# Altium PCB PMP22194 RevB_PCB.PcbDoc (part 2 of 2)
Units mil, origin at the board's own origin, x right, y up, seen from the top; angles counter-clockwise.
Board outline 2100 x 2100 mil, 4 copper layers (Top Layer, Signal Layer 1, Signal Layer 2, Bottom Layer), stack 62.2 mil thick; 70 components, 29 nets, 172 pads, 172 vias.
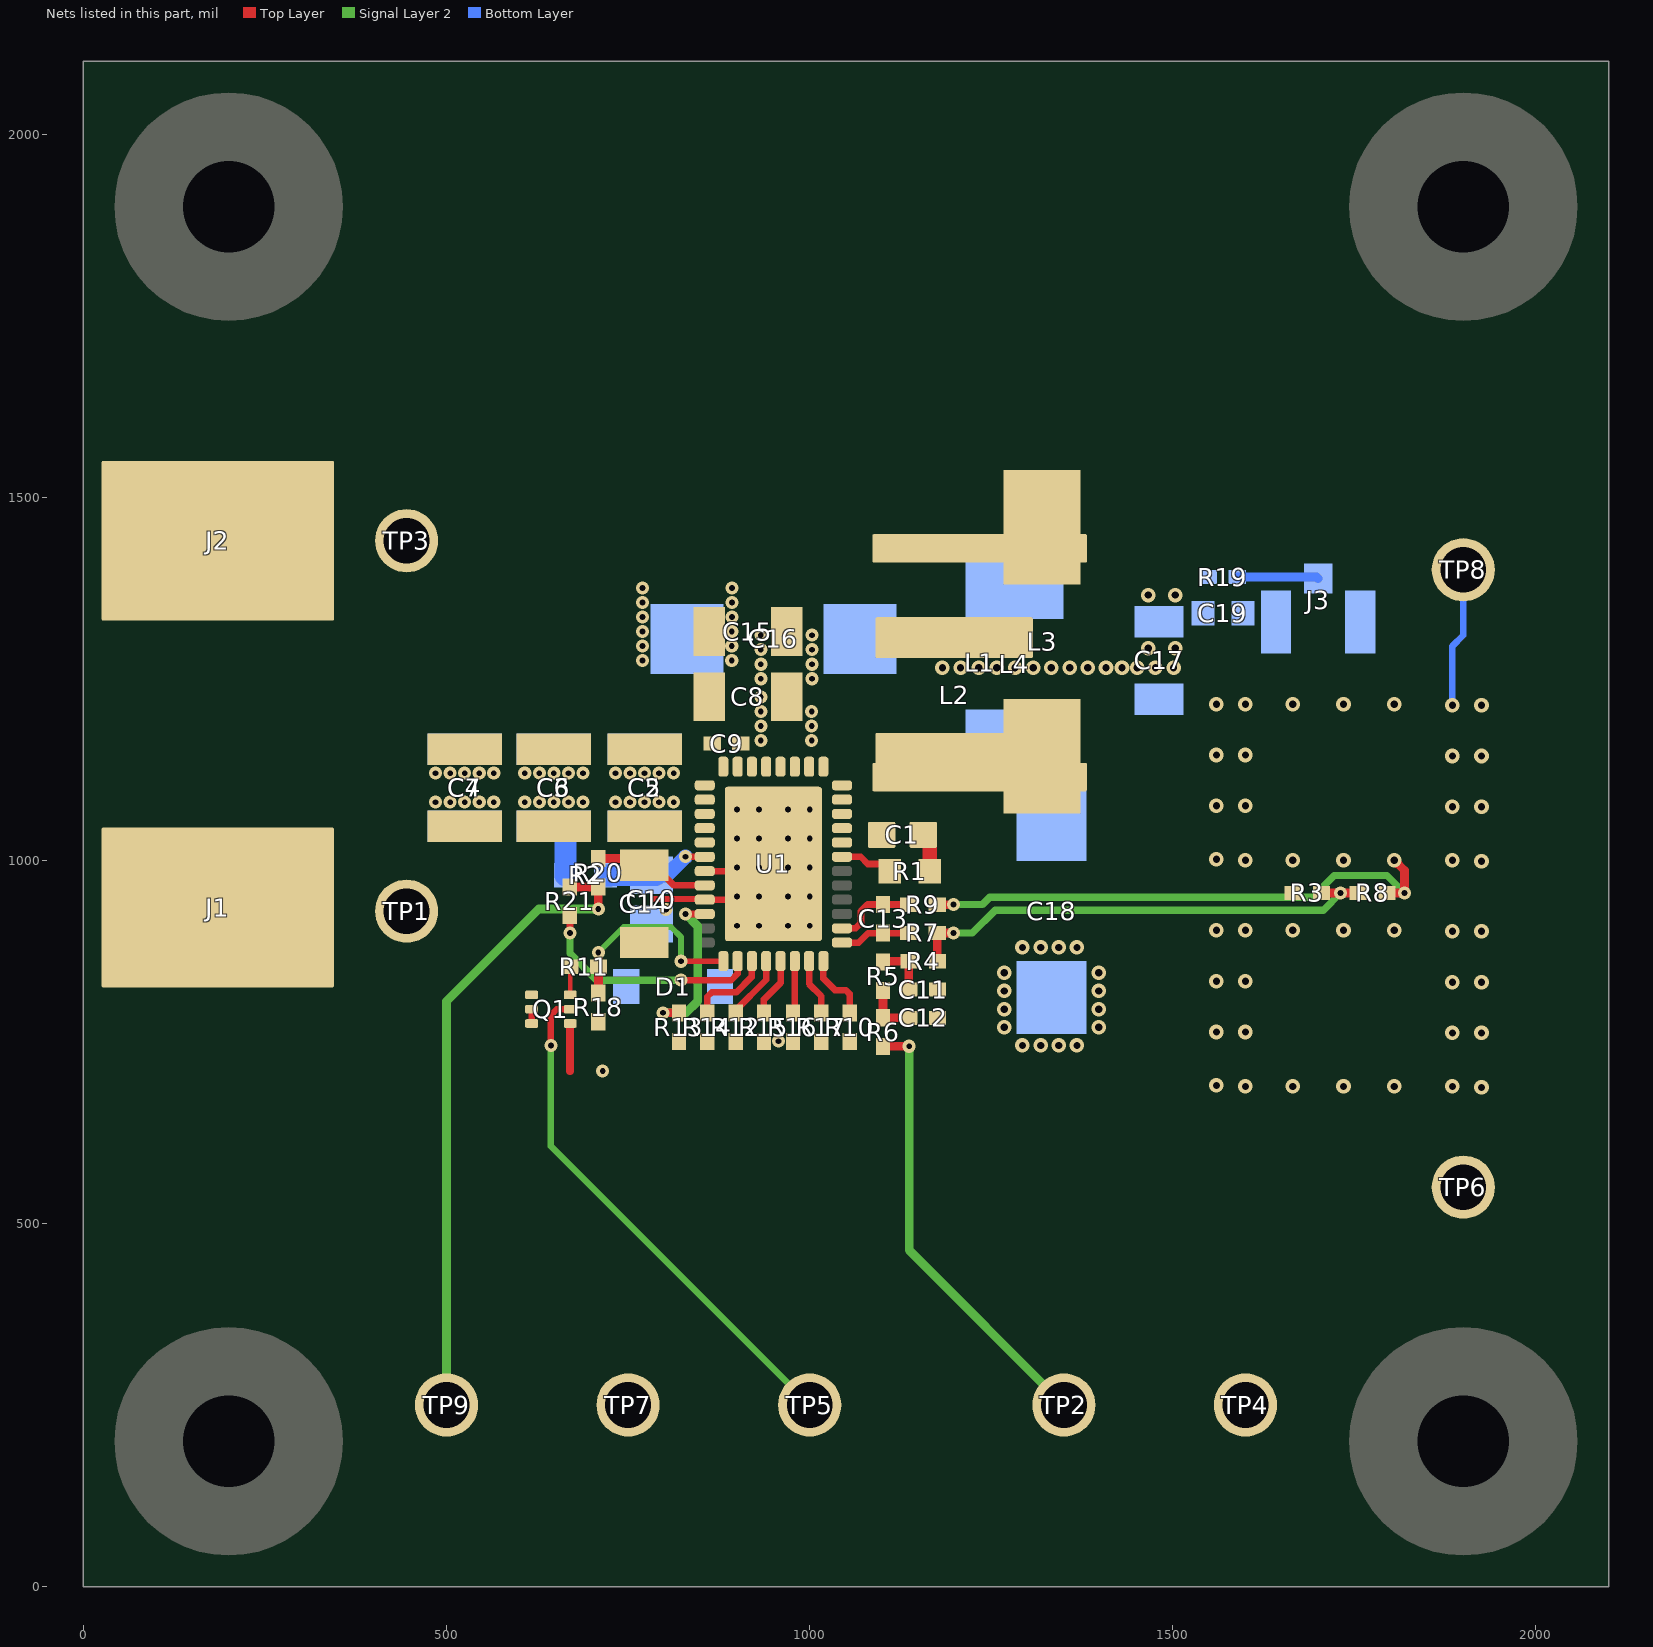
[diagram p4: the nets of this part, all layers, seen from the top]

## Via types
v1: diameter 20, hole 10, Top Layer to Bottom Layer, tented both sides, 78 vias
v2: diameter 18, hole 8, Top Layer to Bottom Layer, tented both sides, 72 vias
v3: diameter 18, hole 8, Top Layer to Bottom Layer, 20 vias
v4: diameter 18, hole 8, Top Layer to Bottom Layer, tented top, 2 vias

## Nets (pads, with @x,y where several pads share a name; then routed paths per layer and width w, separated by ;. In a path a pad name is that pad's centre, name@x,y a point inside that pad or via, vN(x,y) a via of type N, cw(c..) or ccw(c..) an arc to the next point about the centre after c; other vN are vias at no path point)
+Vin: C2.1 C3.1 C4.1 C5.1 C6.1 C7.1 C8.1 C9.1 J1.1 Q1.1 R2.2 TP1.1 U1.21 U1.22 U1.23 U1.24 U1.25 | length 74.3
  Bottom Layer w30: C6.1@647.72,1046.85 663.94,1030.63 R2.2@663.94,979.28
  other v2: 485,1080 505,1080 525,1080 545,1080 565,1080 607.72,1080 627.72,1080 647.72,1080 667.72,1080 687.72,1080 732.72,1080 752.72,1080 772.72,1080 792.72,1080 812.72,1080
-V: C8.2 C9.2 C10.2 C14.2 C15.2 C16.2 D1.2 L4.1 R10.1 R12.1 R13.1 R14.1 R15.2 R16.1 R17.1 R18.1 U1.13 U1.14 U1.15 U1.16 U1.17 U1.18 U1.19 U1.20 U1.27 U1.29 U1.41@950,995 | length 270.5
  Top Layer w8: 785.12,946.88 838.94,946.88 838.94,946.71 854.59,946.71 U1.29@855.51,945.79
  Top Layer w9: U1.29@855.51,945.79 900.79,945.79 U1.41@940.16,985.16 ; U1.27@855.51,985.16 U1.41@940.16,985.16 ; U1.41@950,995 U1.41@940.16,985.16
  other v2: 932.72,1165 1002.72,1165 932.72,1185 1002.72,1185 932.72,1205 1002.72,1205 932.72,1225 932.72,1250 1003,1250 932.72,1270 1003,1270 932.72,1290 1003,1290 932.72,1310 1003,1310
  other v3: 900,910 930,910 970,910 1000,910 900,950 930,950 970,950 1000,950 900,990 930,990 970,990 1000,990 900,1030 930,1030 970,1030 1000,1030 900,1070 930,1070 970,1070 1000,1070
  other v4: 957,751 802,932
-Vo_adj: R6.2 TP2.1 | length 618.3
  Top Layer w12: R6.2@1101,743.81 1101.19,744 v2(1137,744)
  Signal Layer 2 w12: v2(1137,744) 1137,463 TP2.1@1350,250
-Vout: C17.2 C18.2 C19.2 J3.2@1641.93,1328 J3.3@1758.07,1328 L4.2 R8.1 R9.1 TP8.1 | length 937.5
  Top Layer w12: R9.1@1175.68,939 v2(1198,939) ; R8.1@1794.68,955 v2(1819,955) 1819,986 v1(1805,1000)
  Signal Layer 2 w10: v2(1198,939) 1237.73,939 1247.91,949.18 1692.4,949.18 1722.22,979 1795,979 v2(1819,955)
  Bottom Layer w9: v1(1885,1213.63) 1885,1295 1900,1310 TP8.1@1900,1400
  other v1: 1925,998.63 1600,1000 1665,1000 1735,1000 1885,1000 1560,1001.37 1885,1073.63 1925,1073.63 1560,1075 1600,1075 1885,1143.63 1925,1143.63 1560,1145 1600,1145 1925,1213.63 1560,1215 1600,1215 1665,1215 1735,1215 1805,1215
BP: C14.1 R20.2 U1.28 | length 161.8
  Top Layer w9: C14.1@772,993.15 785.51,993.15 813.19,965.47 U1.28@855.51,965.47
  Top Layer w12: R20.2@709,1002.4 762.75,1002.4 C14.1@772,993.15
EN: R11.1 R18.2 U1.33 | length 281.6
  Top Layer w8: v2(823,861) 823.14,861.14 U1.33@881.1,861.14
  Top Layer w12: R18.2@708.72,817.19 709.18,817.65 R11.1@709.18,853.28 709,853.47 v2(709,873)
  Signal Layer 2 w8: v2(709,873) 744.11,908.11 808.89,908.11 823,894 v2(823,861)
GND: C2.2 C3.2 C4.2 C5.2 C6.2 C7.2 C11.2 C12.2 C15.1 C16.1 C17.1 C18.1 C19.1 D1.1 J2.1 L1.2 L2.2 L3.2 Q1.4 R3.2 R19.1 TP3.1 TP4.1 TP6.1 TP7.1 | length 65.7
  Top Layer w11: 670.29,709.57 Q1.4@670.29,775.32
  other v1: 1925,687.25 1600,688.63 1665,688.63 1735,688.63 1805,688.63 1885,688.63 1560,690 1293,745.09 1318,745.09 1343,745.09 1368,745.09 1885,762.25 1925,762.25 1560,763.63 1600,763.63 1268,770.09 1398,770.09 1268,795.09 1398,795.09 1268,820.09 1398,820.09 1885,832.25 1925,832.25 1560,833.63 1600,833.63 1268,845.09 1398,845.09 1293,880.09 1318,880.09 1343,880.09 1368,880.09 1885,902.25 1925,902.25 1560,903.63 1600,903.63 1665,903.63 1735,903.63 1805,903.63 1182.72,1265 1207.72,1265 1232.72,1265 1257.72,1265 1282.72,1265 1307.72,1265 1332.72,1265 1358,1265 1383,1265 1408,1265 1430,1265 1451,1265.15 1476,1265.15 1501,1265.15 1466.28,1292.15 1503.28,1292.15 1466,1365.15 1503.28,1365.15
  other v2: 715,710 485,1120 505,1120 525,1120 545,1120 565,1120 607.72,1120 627.72,1120 647.72,1120 667.72,1120 687.72,1120 732.72,1120 752.72,1120 772.72,1120 792.72,1120 812.72,1120 770,1275 892.72,1275 770,1295 892.72,1295 770,1315 892.72,1315 770,1335 893,1335 770,1355 893,1355 770,1375 893,1375
ILIM: R13.2 U1.30 | length 230.1
  Top Layer w9: v2(828.99,926.01) 829.08,926.1 U1.30@855.51,926.1
  Top Layer w12: v2(798,790) 819.69,790 R13.2@820,789.69
  Signal Layer 2 w12: v2(798,790) 829.79,790 845.87,806.08 845.87,909.13 v2(828.99,926.01)
MODE: R17.2 U1.39 | length 78.4
  Top Layer w9: U1.39@999.21,861.14 999.21,829.79 1016,813 R17.2@1016,789.69
NetC1_2: C1.2 R1.2 | length 53.7
  Top Layer w20: C1.2@1156.34,1035 1165.28,1026.06 R1.2@1165.28,985
NetC11_1: C11.1 R4.2 R5.1 | length 75
  Top Layer w12: R5.1@1101,860.18 1101.82,861 R4.2@1136.53,861 1136.53,822.28 C11.1@1136.82,822
NetC12_1: C12.1 R5.2 R6.1 | length 73.7
  Top Layer w12: R5.2@1101,820.81 R6.1@1101,783.18 1136.26,783.18 1136.63,782.81 C12.1@1136.82,783
NetJ3_1: J3.1 R19.2 | length 112.1
  Bottom Layer w12: R19.2@1588.69,1390 1698.04,1390 J3.1@1700,1388.04
NetQ1_2: Q1.2 Q1.3 | length 19.7
  Top Layer w9: Q1.3@617.14,775.32 Q1.2@617.14,795
NetQ1_5: Q1.5 TP5.1 | length 714.5
  Top Layer w9: v2(643.72,745) 643.72,787.05 651.67,795 Q1.5@670.29,795
  Signal Layer 2 w9: v2(643.72,745) 643.72,606.28 TP5.1@1000,250
NetQ1_6: Q1.6 R11.2 | length 38.8
  Top Layer w6: R11.2@669.81,853.28 670.29,852.81 Q1.6@670.29,814.68
NetR1_1: R1.1 U1.7 | length 73.9
  Top Layer w9: U1.7@1044.49,1004.84 1070.16,1004.84 1080.08,994.92 1100.24,994.92 R1.1@1110.16,985
Pgd: R21.1 U1.34 | length 320.3
  Top Layer w9: v2(823,835) 891.99,834.99 900.79,843.79 U1.34@900.79,861.14
  Top Layer w10: R21.1@669.72,923.82 670,923.53 v2(670,900) 670.43,900 v2@671,900.57
  Signal Layer 2 w10: v2(670,900) 670,872 707,835 v2(823,835)
Pgood: R20.1 R21.2 TP9.1 | length 887
  Top Layer w12: R21.2@669.72,963.19 708.85,963.19 R20.1@709,963.03 v2(709,933)
  Signal Layer 2 w12: TP9.1@500,250 500,806 627,933 v2(709,933)
RAMP: R10.2 U1.40 | length 95.2
  Top Layer w9: U1.40@1018.9,861.14 1018.9,837.1 1034.7,821.3 1049.7,821.3 1055,816 R10.2@1055,789.69
RSN: C13.2 R9.2 U1.2 | length 115
  Top Layer w9: U1.2@1044.49,906.42 1063.23,906.42 1070.64,913.83 1070.64,930.12 1079.7,939.19 C13.2@1101,939.19 1136.13,939.19 R9.2@1136.31,939
RSP: C13.1 R7.2 U1.1 | length 97.3
  Top Layer w9: U1.1@1044.49,886.73 1067.4,886.73 1080.49,899.82 C13.1@1101,899.82 1136.13,899.82 R7.2@1136.31,900
RT: R16.2 U1.38 | length 72.5
  Top Layer w9: R16.2@977,789.69 979.53,792.21 U1.38@979.53,861.14
SS: R15.1 U1.37 | length 80.9
  Top Layer w9: R15.1@937,789.68 937,808.42 959.84,831.26 U1.37@959.84,861.14
SW: C1.1 L1.1 L2.1 L3.1 U1.8 U1.9 U1.10 U1.11 U1.12
SYNC: R14.2 U1.35 | length 116.8
  Top Layer w9: R14.2@859,789.69 859,812 865.12,818.12 898.98,818.12 920.05,839.19 920.05,860.72 U1.35@920.47,861.14
VDD: C10.1 R2.1 U1.26 | length 147.4
  Top Layer w9: v2(829,1005) 829.16,1004.84 U1.26@855.51,1004.84
  Bottom Layer w20: C10.1@788,979.46 803.46,979.46 v2(829,1005)
  Bottom Layer w30: R2.1@719.06,979.28 C10.1@788,979.46 ; R2.1@725.06,979.28 R2.1@725.24,979.46
VFB: R3.1 R4.1 R7.1 R8.2 | length 667.8
  Top Layer w12: R4.1@1175.9,861 1175.68,861.22 R7.1@1175.68,900 v2(1198,900) ; R3.1@1704.68,955 v2(1731,955) R8.2@1755.31,955
  Signal Layer 2 w10: v2(1198,900) 1224,900 1255.31,931.31 1707.31,931.31 v2(1731,955)
VSEL: R12.2 U1.36 | length 88.9
  Top Layer w9: R12.2@898,789.69 898,793.28 940.16,835.44 U1.36@940.16,861.14
pads on no net: H1.1 H2.1 H3.1 H4.1 H5.0 H6.0 H7.0 H8.0 J3.2@1640.94,1328 J3.3@1759.06,1328 LBL1.0 U1.3 U1.4 U1.5 U1.6 U1.31 U1.32 U1.41@917.91,919.41 U1.41@917.91,969.8 U1.41@917.91,1020.2 U1.41@917.91,1070.59 U1.41@982.09,919.41 U1.41@982.09,969.8 U1.41@982.09,1020.2 U1.41@982.09,1070.59

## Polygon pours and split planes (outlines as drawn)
-V on Top Layer "TOP_LAYER_-V2" (solid, remove dead copper, pour order 6): 737,800 727,790 699,790 699,760 740,760 763,737 1066,737 1066,770 807,770 807,924 822,939 868,939 868,953 737,953
-V on Top Layer "TOP_LAYER_-V1" (solid, remove dead copper, pour order 4): 883,889 883,939 844,939 841,942 841,950 844,953 883,953 883,978 844,978 841,981 841,989 844,992 883,992 883,1115 877,1115 874,1118 874,1140 877,1143 893,1143 893,1173 918,1198 918,1350 1017,1350 1017,1143 1023,1143 1026,1140 1026,1117 1023,1114 1017,1114 1017,891 1015,889
-Vout on Top Layer "TOP_LAYER_-Vout" (solid, remove dead copper, pour order 12): 1525,1245 2080,1245 2080,980 1525,980
GND on Top Layer "TOP_LAYER_GND" (solid, remove dead copper, pour order 14): 1164,750 1164,835 1200,835 1200,1055 1407.72,1055 1407.72,1195 1025,1195 1025,1245 902.72,1245 832.72,1245 827.72,1240 827.72,1120 817.72,1110 0,1110 0,2100 2100,2100 2100,0 1205,0 0,0 0,750
+Vin on Top Layer "TOP_LAYER_+VIN" (solid, remove dead copper, pour order 10): 590,810 625,810 625,965 685,1025 827.72,1025 834.72,1018 870.72,1018 870.72,1148 882.72,1160 882.72,1230 837.72,1230 837.72,1157.6 837.72,1105 827.72,1095 0,1095 0,775 590,775
SW on Top Layer "TOP_LAYER_SW" (solid, remove dead copper, pour order 2): 1031,1103 1031,1131 1080,1180 1260,1180 1260,1225 1385,1225 1385,1165 1385,1090 1132.72,1090 1117.72,1075 1117.72,1018 1031,1018
GND on Bottom Layer "BOTTOM_LAYER_GND" (solid, remove dead copper, pour order 26): 0.63,2102 2100.63,2102 2100.63,2 0.63,2
-Vout on Bottom Layer "BOTTOM_LAYER_-Vout" (solid, remove dead copper, pour order 24): 1580,1245 1580,1370 1780,1370 1780,1245 1950,1245 1950,980 1290,980 1167.72,1102.28 1167.72,1240 1172.72,1245
-V on Bottom Layer "BOTTOM_LAYER_-V" (solid, remove dead copper, pour order 22): 860,800 845,815 845,855 825,875 797,875 746.03,875 746.19,939.85 831,940 850,959 850,978 850,1167.28 917.72,1235 917.72,1317.72 1035,1435 1355,1435 1355,1322.28 1322.72,1290 1162.72,1290 1027.72,1155 1027.72,960 1097.72,890 1097.72,800
+Vin on Bottom Layer "Bottom_LAYER_+VIN" (solid, remove dead copper, pour order 20): 827.72,1025 737.72,1025 470,1025 470,1095 577.72,1095 827.72,1095
-V on Signal Layer 1 "SIGNAL_LAYER_-V" (solid, remove dead copper, pour order 16): 0,0 0,2100 2100,2100 2100,0
GND on Signal Layer 2 "SIGNAL_LAYER_2_GND" (solid, remove dead copper, pour order 18): 0,0 0,2100 2100,2100 2100,0

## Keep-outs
Keep-Out Layer:
  text ".Layer_Name" at 577,-858.49 h60

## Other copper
Top Layer:
  text ".Layer_Name" at 577,-858.49 h60
Bottom Layer:
  text ".Layer_Name" at 577,-858.49 h60

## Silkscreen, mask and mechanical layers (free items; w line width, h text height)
Top Overlay:
  lines w5: 670,943 670,944 ; 689,853 690,853 ; 709,797 709,798 ; 709,982 709,983 ; 860,770 860,771 ; 885,1160 886,1160 ; 938,770 938,771 ; 977,770 977,771 ; 1016,770 1016,771 ; 1101,763 1101,764 ; 1101,840 1101,841 ; 1101,919 1101,920 ; 1125.5,1036 1131,1036 ; 1156,783 1157,783 ; 1156,822 1157,822 ; 1156,861 1157,861 ; 1156,900 1157,900 ; 1156,939 1157,939 ; 1684.5,955 1685.5,955 ; 1775,955 1776,955
  text "'.PRJ_Number'.PCB_Rev" at 797.88,1905 h108.27
  text "-Vout" at 1651,1278 h72.83
  text "GND" at 1673,606 h72.83
  text ".Layer_Name" at 577,-858.49 h60
Bottom Overlay:
  lines w5: 691,980 692,980
  text ".Layer_Name" at 577,-858.49 h60
Top Paste:
  text ".Layer_Name" at 577,-858.49 h60
Bottom Paste:
  text ".Layer_Name" at 577,-858.49 h60
Top Solder:
  rectangle: 1615,705 1870,885
  rectangle: 1615,1020 1870,1200
  text ".Layer_Name" at 577,-858.49 h60
  text ".Layer_Name" at 577,-858.49 h60
Bottom Solder:
  text ".Layer_Name" at 577,-858.49 h60
Drill Guide:
  text ".Layer_Name" at 577,-858.49 h60
M1 Board Outline:
  the board outline again, w10
  text ".Layer_Name" at 577,-858.49 h60
M2 Board Dimensions:
  rectangle: 0,-275 125,-150
  rectangle: 125,-400 500,-275
  lines w7: 0,-275 1000,-275 ; 125,-400 125,-150 ; 250,-400 250,-150 ; 500,-400 500,-150 ; 750,-400 750,-150 ; 0,-400 1000,-400 1000,-150 0,-150 0,-400
  text ".Layer_Name" at 577,-858.49 h60
M3 3D STEP Top:
  text ".Layer_Name" at 577,-858.49 h60
M4 3D STEP Bottom:
  text ".Layer_Name" at 577,-858.49 h60
M5 Assembly Top:
  lines w10: -292,-930.17 6308,-930.17 ; -292,-726.83 6310,-726.83 ; -292,-523.5 -292,-1133.5 3713,-1133.5 6310,-1133.5 6310,-523.5 -291.5,-523.5 -291.5,-1133.5 1284,-1133.5 ; 2173,-1133.5 2173,-523.5 ; 3440,-726.83 3440,-523.5 ; 4280,-726.83 4280,-523.5 ; 4902,-1140 4902,-937.17
  text "COMPONENTS MARKED 'DNP' SHOULD NOT BE POPULATED." at 1153.5,-318.5 h60
  text "ASSEMBLY VARIANT:" at 1153,-434 h60
  text ".VariantName" at 2189,-434 h60
  text "PCB VIEWED FROM TOP SIDE" at -228.5,-655.67 h60
  text "BOARD #:" at 2248,-655.67 h60
  text ".PRJ_Number" at 2793.5,-655.67 h60
  text "REV:" at 3638,-655.67 h60
  text ".PCB_Rev" at 3929.5,-655.67 h60
  text "SVN REV:" at 4476,-655.67 h60
  text ".VersionControl_RevNumber" at 4982,-655.67 h60
  text "TID #:" at 2248,-859 h60
  text ".TID" at 2793.5,-859 h60
  text "PLOT NAME =" at -228.5,-1064.34 h60
  text ".plot_File_Name" at 577,-1064.34 h60
  text "GENERATED    :" at 2250,-1064.34 h60
  text ".Print_Date" at 3119.5,-1064.34 h60
  text ".Print_Time" at 3848.5,-1064.34 h60
  text "TEXAS INSTRUMENTS" at 5113,-1064.34 h60
M6 Assembly Bottom:
  lines w10: -292.5,-727.33 6309.5,-727.33 ; -290.5,-930.67 6309.5,-930.67 ; 1115.5,-1140.5 1115.5,-937.67 ; 1737.5,-727.33 1737.5,-524 ; 2577.5,-727.33 2577.5,-524 ; 3844.5,-1134 3844.5,-524 ; 4733.5,-1134 6309,-1134 6309,-524 -292.5,-524 -292.5,-1134 2304.5,-1134 6309.5,-1134 6309.5,-524
  text "COMPONENTS MARKED 'DNP' SHOULD NOT BE POPULATED." at 6102,-318 h60
  text ".VariantName" at 5058,-434 h60
  text "ASSEMBLY VARIANT:" at 6097,-434 h60
  text ".VersionControl_RevNumber" at 1035.5,-656.17 h60
  text "SVN REV:" at 1541.5,-656.17 h60
  text ".PCB_Rev" at 2088,-656.17 h60
  text "REV:" at 2379.5,-656.17 h60
  text ".PRJ_Number" at 3224,-656.17 h60
  text "BOARD #:" at 3769.5,-656.17 h60
  text "PCB VIEWED FROM BOTTOM SIDE" at 6246,-656.17 h60
  text ".TID" at 3224,-859.5 h60
  text "TID #:" at 3769.5,-859.5 h60
  text "TEXAS INSTRUMENTS" at 904.5,-1064.84 h60
  text ".Print_Time" at 2169,-1064.84 h60
  text ".Print_Date" at 2898,-1064.84 h60
  text "GENERATED    :" at 3767.5,-1064.84 h60
  text ".plot_File_Name" at 5440.5,-1064.84 h60
  text "PLOT NAME =" at 6246,-1064.84 h60
M9 Title Sheet:
  drawing of 57 lines, arcs and shapes, not listed
  text "1" at 739.84,8036.5 h70
  text "2" at 3235.5,8036.5 h70
  text "3" at 5724.84,8036.5 h70
  text "4" at 8231.51,8036.5 h70
  text "5" at 10730.5,8036.5 h70
  text "6" at 13235.5,8036.5 h70
  text "A" at -416.5,6893.5 h70
  text "A" at 14383.5,6893.5 h70
  text "B" at -416.5,4513.5 h70
  text "B" at 14383.5,4513.5 h70
  text "C" at -416.5,2138.5 h70
  text "C" at 14383.5,2138.5 h70
  text "PROJECT TITLE:" at 11343.5,277.5 h45
  text ".PRJ_Title" at 11393.5,144.17 h70
  text "DESIGNED FOR:" at 11343.5,-23.5 h45
  text ".PRJ_Customer" at 11393.5,-163.5 h70
  text "D" at -416.5,-231.5 h70
  text "D" at 14383.5,-231.5 h70
  text "FILE NAME:" at 11343.5,-323.5 h45
  text ".PCB_File_Name_No_Path" at 11393.5,-443.5 h70
  text "Texas Instruments (TI) and/or its licensors do not warrant the accuracy or completeness of this specification" at 6374,-605.34 h45
  text "ENGINEER:" at 11343.5,-613.5 h45
  text "LAYOUT BY:" at 12848.5,-613.5 h45
  text "or any information contained therein. TI and/or its licensors do not warrant that this design will meet" at 6329.01,-718 h45
  text ".PRJ_Engineer" at 11393.5,-768.49 h70
  text ".PCB_Layout" at 12899,-768.49 h70
  text "the specifications, will be suitable for your application or fit for any particular purpose, or will operate in" at 6329.01,-830.67 h45
  text ".Layer_Name" at 577,-858.49 h60
  text "ALTIUM DESIGNER VERSION:" at 12848.5,-923.5 h45
  text "an implementation. TI and/or its licensors do not warrant that the design is production worthy. You should" at 6329.01,-943.33 h45
  text "completely validate and test your design implementation to confirm the system functionality for your application." at 6374,-1056 h45
  text ".print_Scale" at 11393.5,-1056.83 h70
  text ".Application_BuildNumber" at 12899,-1056.83 h70
  text "1" at 739.84,-1263.5 h70
  text "2" at 3235.5,-1263.5 h70
  text "3" at 5724.84,-1263.5 h70
  text "4" at 8231.51,-1263.5 h70
  text "5" at 10730.5,-1263.5 h70
  text "6" at 13235.5,-1263.5 h70
M10 Fab Notes:
  drawing of 189 lines, arcs and shapes, not listed
  text "DESIGN INFORMATION" at 12382.02,6356.17 h60
  text "MIN. TRACK WIDTH:" at 11737.46,6224.05 h60
  text "6" at 12833.7,6224.05 h60
  text "MIL" at 12988.46,6224.05 h60
  text "MIN. CLEARANCE:" at 11737.46,6099.92 h60
  text "0.2" at 12773.7,6099.93 h60
  text "mm" at 12988.46,6099.92 h60
  text "18" at 12798,5978 h60
  text "MIN. VIA PAD SIZE:" at 11737.46,5975.8 h60
  text "MIL" at 12988.46,5975.8 h60
  text "0.127mm (5MIL)" at 12432.46,5845.9 h60
  text "MINIMUM ANNULAR RING" at 11408.23,5837.67 h60
  text "EXTERNAL" at 13140.46,5837.67 h60
  text "PER" at 11608.23,5727.55 h60
  text "IPC-D-275 CLASS 2 LEVEL C" at 11828.23,5727.54 h60
  text "MIL, HOLES" at 13316.46,5627.07 h60
  text "+/-" at 12924,5618.48 h60
  text "+/-" at 13778,5618.48 h60
  text "REGISTRATION TOLERANCES:" at 11408.23,5617.42 h60
  text "METAL" at 12608,5617.42 h60
  text "5" at 13184.2,5617.42 h60
  text "3" at 14017.2,5617.42 h60
  text "MIL" at 14133.46,5617.42 h60
  text "HOLE SIZE TOLERANCE (UNLESS OTHERWISE SPECIFIED):" at 11408.23,5519.1 h60
  text "+/-" at 13778,5516.23 h60
  text "3" at 14017.2,5515.17 h60
  text "MIL" at 14133.46,5515.17 h60
  text "MATERIAL:" at 11333.46,5377.52 h60
  text "FR-4 High Tg" at 12319.9,5249 h60
  text "X" at 12175.46,5241.01 h60
  text "FR-408" at 11754.46,5236.49 h60
  text "OTHER" at 13242.46,5236.49 h60
  text "62 MIL (1.6mm) +/-10%" at 12074.56,5093.46 h60
  text "X" at 11954.46,5091.01 h60
  text "THICKNESS:" at 11408.23,5085.24 h60
  text "OTHER" at 13359.46,5085.24 h60
  text "TOLERANCE:" at 11408.23,4946.92 h60
  text "X" at 12256.46,4946.92 h60
  text "ANSI IPC-6012 TYPE 3 CLASS 2" at 12434.48,4946.92 h60
  text "OTHER +/-" at 12434.46,4802.73 h60
  text "BOW & TWIST:" at 11408.23,4657.54 h60
  text "X" at 12256.46,4657.54 h60
  text "ANSI IPC-6012 TYPE 3 CLASS 2" at 12434.48,4657.54 h60
  text "OTHER +/-" at 12434.46,4510.85 h60
  text "DRILLING:" at 11333.46,4380.23 h60
  text "NC_DRILL FILES" at 13094.46,4275.04 h60
  text "REFERENCE:" at 11408.23,4271.1 h60
  text "X" at 12065.46,4271.01 h60
  text "AS SHOWN" at 12243.46,4271.1 h60
  text "X" at 12966.46,4271.1 h60
  text "OTHER" at 13392.46,4128.85 h60
  text "PTH COPPER THICKNESS:" at 11407.91,4125.32 h60
  text "X" at 12547.14,4125.32 h60
  text "20-30 um" at 12675.14,4125.32 h60
  text "BOARD FINISH:" at 11333.46,3977.73 h60
  text "SILKSCREEN:" at 11488.68,3867.6 h60
  text "X" at 12446.46,3867.6 h60
  text "TOP" at 12563.46,3867.6 h60
  text "X" at 12956.46,3867.6 h60
  text "BOTTOM" at 13074.46,3867.6 h60
  text "SILKSCREEN COLOR:" at 11488.68,3712.41 h60
  text "X" at 12445.46,3712.41 h60
  text "WHITE" at 12563.46,3712.41 h60
  text "OTHER" at 13074.46,3712.41 h60
  text "X" at 12576.46,3568.96 h60
  text "GREEN" at 12694.46,3568.96 h60
  text "OTHER" at 13312.46,3568.96 h60
  text "SOLDER RESIST COLOR:" at 11488.68,3562.1 h60
  text "X" at 12576.46,3414.71 h60
  text "MATTE" at 12694.46,3414.71 h60
  text "SEMI-GLOSS" at 13312,3414.07 h60
  text "IMMERSION GOLD (ENIG)" at 12394.46,3241.94 h60
  text "ENEPIG" at 13732,3234.72 h60
  text "SURFACE FINISH:" at 11333.46,3233.72 h60
  text "X" at 12216.46,3233.72 h60
  text "IMM. TIN/SILVER OR EQUIV" at 11663,3096.4 h60
  text "OTHER" at 13094.46,3092.47 h60
  text "ARRAY/PANEL:" at 11333.46,2937.09 h60
  text "X" at 12210,2928.87 h60
  text "CUT AND TRIM PER M1 BOARD OUTLINE" at 12394.46,2928.87 h60
  text "N.C. ROUTE" at 12394.46,2792.9 h60
  text "V. SCORE" at 13260.46,2792.9 h60
  text "CERTIFICATION:" at 11333.46,2663.77 h60
  text "MATERIALS AND WORKMANSHIP FOR ALL PCBS" at 12058.46,2663.77 h60
  text "TO MEET OR EXCEED THE REQUIREMENTS OF:" at 12058.46,2569.71 h60
  text "X" at 11695.97,2441.08 h60
  text "ANSI IPC-A-600F CLASS ->" at 11823.96,2441.08 h60
  text "X" at 13471.97,2441.08 h60
  text "2" at 13581.96,2441.08 h60
  text "1" at 13266.96,2439.58 h60
  text "3" at 13935.96,2439.58 h60
  text "X" at 12507.97,2293.39 h60
  text "RoHS" at 12635.96,2293.39 h60
  text "OTHER" at 13280.36,2293.39 h60
  text "PER ORDER" at 13677.42,2293.39 h60
  text "ALL BOARDS MUST MEET OR EXCEED UL94-V0 REQUIREMENTS." at 11361,2139.57 h60
  text "PCB MUST BEAR THE UL94V-0 UL REGISTERED MATERIAL ID NUMBER" at 11361,2023.5 h60
  text "ADDITIONAL REQUIREMENTS:" at 11333.46,1854.08 h60
  text "MICROSECTION:" at 11408.23,1746.95 h60
  text "YES" at 12313.96,1746.95 h60
  text "REQUIRED" at 13175.46,1602.62 h60
  text "BARE BOARD ELEC. TEST:" at 11408.23,1599.76 h60
  text "NONE" at 12713.96,1599.76 h60
  text "X" at 13057.46,1599.76 h60
  text "PER ORDER" at 13767.46,1599.76 h60
  text "XX MIL VIAS REQUIRE NON-CONDUCTIVE FILL AND PLANARIZE" at 11576.38,1394.82 h59
  text "XX MIL VIAS REQUIRE CONDUCTIVE FILL AND PLANARIZE" at 11584.38,1290.84 h60
  text "OUTER XX MIL TRACES REQUIRE 50 OHM SINGLE-ENDED IMPEDANCE" at 11583.39,1127.46 h58
  text "LAYER 2 & 3 (INNER LAYERS) XX MIL WIDE, XX MIL SPACE / TRACES REQUIRE 100 OHM DIFFERENTIAL IMPEDANCE" at 11575.39,891.74 h60
  text ".Layer_Name" at 577,-858.49 h60
M11 Gerber Information:
  lines w10: -292,-930.17 6308,-930.17 ; -292,-726.83 6310,-726.83 ; -292,-523.5 -292,-1133.5 3713,-1133.5 6310,-1133.5 6310,-523.5 -291.5,-523.5 -291.5,-1133.5 1284,-1133.5 ; 2173,-1133.5 2173,-523.5 ; 3440,-726.83 3440,-523.5 ; 4280,-726.83 4280,-523.5 ; 4902,-1140 4902,-937.17
  text "ALL ARTWORK VIEWED FROM TOP SIDE" at -228.5,-655.67 h60
  text "BOARD #:" at 2248,-655.67 h60
  text ".PRJ_Number" at 2793.5,-655.67 h60
  text "REV:" at 3638,-655.67 h60
  text ".PCB_Rev" at 3929.5,-655.67 h60
  text "SVN REV:" at 4476,-655.67 h60
  text ".VersionControl_RevNumber" at 4982,-655.67 h60
  text "LAYER NAME =" at -228.5,-858.49 h60
  text "TID #:" at 2248,-859 h60
  text ".TID" at 2793.5,-859 h60
  text "PLOT NAME =" at -228.5,-1064.34 h60
  text ".plot_File_Name" at 577,-1064.34 h60
  text "GENERATED    :" at 2250,-1064.34 h60
  text ".Print_Date" at 3119.5,-1064.34 h60
  text ".Print_Time" at 3848.5,-1064.34 h60
  text "TEXAS INSTRUMENTS" at 5113,-1064.34 h60
M12 Stackup:
  drawing of 295 lines, arcs and shapes, not listed
  text "Layer" at 9770.35,7840 h60
  text "Name" at 10180.26,7840 h60
  text "Material" at 11120,7840 h60
  text "Thickness" at 11979.77,7840 h60
  text "Constant" at 12629.6,7840 h60
  text "Board Layer Stack" at 13199.46,7840 h60
  text "1" at 9770.35,7720 h60
  text "Top Overlay" at 10180.26,7720 h60
  text "2" at 9770.35,7600 h60
  text "Top Solder" at 10180.26,7600 h60
  text "Solder Resist" at 11120,7600 h60
  text "0.40mil" at 11979.77,7600 h60
  text "3.5" at 12629.6,7600 h60
  text "3" at 9770.35,7480 h60
  text "Top Layer" at 10180.26,7480 h60
  text "Copper" at 11120,7480 h60
  text "2.80mil" at 11979.77,7480 h60
  text "4" at 9770.35,7360 h60
  text "Dielectric 1" at 10180.26,7360 h60
  text "8.00mil" at 11979.77,7360 h60
  text "4.2" at 12629.6,7360 h60
  text "5" at 9770.35,7240 h60
  text "Signal Layer 1" at 10180.26,7240 h60
  text "Copper" at 11120,7240 h60
  text "2.80mil" at 11979.77,7240 h60
  text "6" at 9770.35,7120 h60
  text "Dielectric2" at 10180.26,7120 h60
  text "FR-4" at 11120,7120 h60
  text "35.00mil" at 11979.77,7120 h60
  text "4.8" at 12629.6,7120 h60
  text "7" at 9770.35,7000 h60
  text "Signal Layer 2" at 10180.26,7000 h60
  text "Copper" at 11120,7000 h60
  text "2.80mil" at 11979.77,7000 h60
  text "8" at 9770.35,6880 h60
  text "Dielectric 3" at 10180.26,6880 h60
  text "8.00mil" at 11979.77,6880 h60
  text "4.2" at 12629.6,6880 h60
  text "9" at 9770.35,6760 h60
  text "Bottom Layer" at 10180.26,6760 h60
  text "Copper" at 11120,6760 h60
  text "2.80mil" at 11979.77,6760 h60
  text "10" at 9770.35,6640 h60
  text "Bottom Solder" at 10180.26,6640 h60
  text "Solder Resist" at 11120,6640 h60
  text "0.40mil" at 11979.77,6640 h60
  text "3.5" at 12629.6,6640 h60
  text "11" at 9770.35,6520 h60
  text "Bottom Overlay" at 10180.26,6520 h60
  text ".Layer_Name" at 577,-858.49 h60
M13 Component Bodies Top:
  text ".Layer_Name" at 577,-858.49 h60
M14 Component Bodies Bottom:
  text ".Layer_Name" at 577,-858.49 h60
M15 Courtyards Top:
  text ".Layer_Name" at 577,-858.49 h60
M16 Courtyards Bottom:
  text ".Layer_Name" at 577,-858.49 h60
Drill Drawing:
  circle w10: c5363.73,3374.26 r27.63
  lines w10: 5336.1,2973.62 5363.73,2987.44 5391.36,2973.62 5377.54,3001.25 5391.36,3028.88 5363.73,3015.07 5336.1,3028.88 5349.91,3001.25 5336.1,2973.62 ; 5336.1,3097.96 5391.36,3097.96 5391.36,3153.22 5336.1,3153.22 5336.1,3097.96 ; 5336.1,3236.11 5349.91,3236.11 5363.73,3222.29 5377.54,3236.11 5391.36,3236.11 5377.54,3249.92 5391.36,3263.74 5377.54,3263.74 5363.73,3277.55 5349.91,3263.74 5336.1,3263.74 5349.91,3249.92 5336.1,3236.11
  lines w12: 5286,2936.32 8516.06,2936.32 ; 5286,3433.66 8516.06,3433.66 ; 5623.75,2811.99 5623.75,3558 ; 5955.56,2811.99 5955.56,3558 ; 6591.66,2811.99 6591.66,3558 ; 6850.66,2811.99 6850.66,3558 ; 7225.64,2811.99 7225.64,3558 ; 7949.86,2811.99 7949.86,3558 ; 5286,2811.99 8516.06,2811.99 8516.06,3558 5286,3558 5286,2811.99
  text "Symbol" at 5360.6,3470.96 h72
  text "Quantity" at 5661.05,3470.96 h72
  text "Finished Hole Size" at 5992.86,3470.96 h72
  text "Plated" at 6628.96,3470.96 h72
  text "Hole Type" at 6887.96,3470.96 h72
  text "Drill Layer Pair" at 7262.94,3470.96 h72
  text "Hole Tolerance" at 7987.16,3470.96 h72
  text "94" at 5661.05,3346.63 h60
  text "8.00mil (0.203mm)" at 5992.86,3346.63 h60
  text "PTH" at 6628.96,3346.63 h60
  text "Round" at 6887.96,3346.63 h60
  text "Top Layer - Bottom Layer" at 7262.94,3346.63 h60
  text "78" at 5661.05,3222.29 h60
  text "10.00mil (0.254mm)" at 5992.86,3222.29 h60
  text "PTH" at 6628.96,3222.29 h60
  text "Round" at 6887.96,3222.29 h60
  text "Top Layer - Bottom Layer" at 7262.94,3222.29 h60
  text "9" at 5661.05,3097.96 h60
  text "63.00mil (1.600mm)" at 5992.86,3097.96 h60
  text "PTH" at 6628.96,3097.96 h60
  text "Round" at 6887.96,3097.96 h60
  text "Top Layer - Bottom Layer" at 7262.94,3097.96 h60
  text "4" at 5661.05,2973.62 h60
  text "125.98mil (3.200mm)" at 5992.86,2973.62 h60
  text "PTH" at 6628.96,2973.62 h60
  text "Round" at 6887.96,2973.62 h60
  text "Top Layer - Bottom Layer" at 7262.94,2973.62 h60
  text "185 Total" at 5661.05,2849.29 h60
  text ".Layer_Name" at 577,-858.49 h60
M17 Embedded Cavity:
  text ".Layer_Name" at 577,-858.49 h60
M18 Embedded Assembly:
  text ".Layer_Name" at 577,-858.49 h60
M19 Embedded Keepout:
  text ".Layer_Name" at 577,-858.49 h60

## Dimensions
0,-400 to 1000,-400 on M2 Board Dimensions
0,0 to 0,2100 on M2 Board Dimensions
0,0 to 2100,0 on M2 Board Dimensions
